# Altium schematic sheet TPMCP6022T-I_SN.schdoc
size 127 x 101 mm
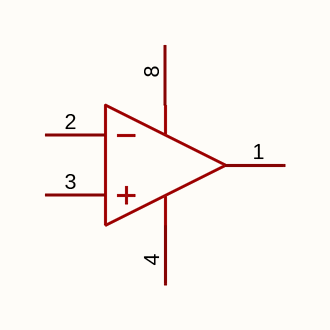
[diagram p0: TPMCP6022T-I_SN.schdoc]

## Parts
U?  tpmcp6022t-i/sn  [SOP-8_L4.9-W3.9-P1.27-LS6.0-BL]  (value not drawn)  (part A of 2)

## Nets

Not connected (* = marked no-connect by the designer): U? 1(OUTA) 2(INA-) 3(INA+) 4(-VS) 8(+VS)

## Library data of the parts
U? = tpmcp6022t-i/sn: 放大器数:2;轨到轨:轨到轨输入,轨到轨输出;增益带宽积(GBW):10MHz;输入失调电压(Vos):5mV;压摆率(SR):4.5V/us;输入偏置电流(Ib):100pA;; Manufacturer: TECH PUBLIC(台舟); AddInBom: yes; ModelId: 75c24a7891ee4dd6bdac16a7163ff87e; ModelName: SOP-8_L4.9-W3.9-P1.27-LS6.0-BL-1; ModelTransform: 192.913,236.22,0,0,0,0,-0.393,2.749,0; Number of Channels: 2; Maximum Power Supply Range (Vdd-Vss): 7V; Gain Bandwidth Product: 10MHz; Vos - Input Offset Voltage: 5mV; Input Offset Voltage Drift(Vos TC): 6uV/℃; Ib - Input Bias Current: 100pA; Input Offset Current(Ios): 1pA; Input Voltage Noise Density: 30nV/√Hz@1kHz; Common Mode Rejection Ratio(CMRR): 80dB; Quiescent Current: 800uA; Output Current: 50mA; Single supply: 2.2V~5.5V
